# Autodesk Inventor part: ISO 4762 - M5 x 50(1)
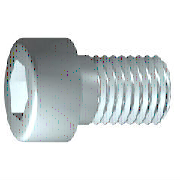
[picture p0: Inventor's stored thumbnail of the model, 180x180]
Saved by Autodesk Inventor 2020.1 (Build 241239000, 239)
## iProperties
Created: 2019-01
Part Number: ISO 4762 - M5 x 50(1)
Material: Edelstahl, 440C
Description: Innensechskantschraube
Document SubType Name: Modeling
Standard: ISO 4762
Designer: lutzd
Standard Revision: Fourth edition 2004-03-01
Standards Organization: ISO
Language: de-DE
Size Designation: M5 x 50
Categories: <MemberInstance><Categories><Category DisplayName="Verbindungselemente" InternalName="e4da775c-781d-43d5-af7c-5136215cf5a6" Mnemonic="FSTN"><Category DisplayNam
Mass: 9.45857 g
Surface Area: 10.5948 cm^2
Volume: 1.22046 cm^3
Density: 7.75 g/cm^3
Appearance: Halbpoliert
IsCustomPart: 0
Author: lutzd
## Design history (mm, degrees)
workplane "Work Plane1"
fillet "Fillet2" dims "d30" = 0.1 (= R)
sketch "Skizze1"
  geometry: L1 (-1.167, 0)-(50, 0); L2 (50, 0)-(50, 2.5); L3 (50, 2.5)-(28, 2.5); L4 (28, 2.5)-(27.509, 2.5); L5 (27.509, 2.5)-(0, 2.5); L6 (0, 2.5)-(0, 4.25); L7 (0, 4.25)-(-5, 4.25); L8 (-5, 4.25)-(-5, 2.309); L9 (-5, 2.309)-(-2.5, 2.309); L10 (-2.5, 2.309)-(-1.167, 0); L11 (-16, 0)-(61, 0) reference; L12 (0, -0.85)-(0, 5.1) reference; L13 (28, 2.5)-(0, 2.5)
  constraints: 22 end point, 6 parallel, 2 collinear, 2 perpendicular, 1 horizontal, 1 point on line
  dimensions: "d1" = 22 distance from line of L3.end L2 (= GEL); "d2" = 0.49086 distance of L4.end L3.end (computed from GAL); "d3" = 5 distance between parallel lines of L8 L6 (= KOH); "d4" = 2.5 distance of L8.end L9.end (= INTI); "d5" = 60 deg angle of L10 L1; "d6" = 5 diameter of L3 L1 (= GD); "d7" = 5 diameter of L5 L1 (= BDM); "d8" = 4.6188 diameter of L9 L1 (= 1.1547 x SW); "d9" = 8.5 diameter of L7 L1 (= KOD); "d26" = 50 distance between parallel lines of L12 L2 (= NLG)
revolve "Körper" sketch "Skizze1" stored, may be unused: angle "d10" = 90 deg
sketch "Skizze2"
  geometry: L1 (0, -5.95)-(0, 5.95) reference; L2 (-5.95, 0)-(5.95, 0) reference; L3 (2.309, 0)-(1.155, -2); L4 (1.155, -2)-(-1.155, -2); L5 (-1.155, -2)-(-2.309, 0); L6 (-2.309, 0)-(-1.155, 2); L7 (-1.155, 2)-(1.155, 2); L8 (1.155, 2)-(2.309, 0); 2 further points
  constraints: 12 end point, 1 coincident, 1 horizontal alignment, 1 point on line, 12 other
extrude "Loch" join sketch "Skizze2" stored distance "d11" = 10; taper "d12" = 0 deg
body "Solid1"
fillet "Rundung1" dims "d17" = 0.5 (= RR)
feature "Gewinde" dims "d13" = 22 (= GEL), "d14" = 0
chamfer "Fase1" distance "d15" = 0.49076 (= -0.5 x SPD + 0.5 x GD); stored, may be unused: second distance "d16" = 0.49076 (= GUL), angle "d27" = 45 deg
other parameters: "GD" = 5 [user parameter; used in 2 equation terms], "NLG" = 50 [user parameter; used in 1 equation term], "GEL" = 22 [user parameter; used in 2 equation terms], "KOD" = 8.5 [user parameter; used in 1 equation term], "KOH" = 5 [user parameter; used in 1 equation term], "INTI" = 2.5 [user parameter; used in 1 equation term], "GAL" = 0.49076 (= 0.61345 x PTC) [user parameter; used in 1 equation term], "GUL" = 0.49076 (= 0.61345 x PTC) [user parameter; used in 1 equation term], "BDM" = 5 (= NND) [user parameter; used in 1 equation term], "SW" = 4 [user parameter; used in 2 equation terms], "RR" = 0.5 [user parameter; used in 1 equation term], "SPD" = 4.01848 (= NND - 1.2269 x PTC) [user parameter; used in 1 equation term], "d19" = 0, "d28" = 0, "d29" = 0, "R" = 0.1 [user parameter; used in 1 equation term], "TOA" = 30 deg [user parameter], "GD1" = 4.01848 (= THREADDIA - 1.2269 x PTC) [user parameter], "THREADDIA" = 5 [user parameter; used in 1 equation term], "FAWI" = 45 deg [user parameter], "TPU" = 12.5 (computed from PTC) [user parameter], "PTC" = 0.8 [user parameter; used in 5 equation terms], "NND" = 5 [user parameter; used in 2 equation terms], "E0" = 4.62 (= 1.155 x SW) [user parameter]
